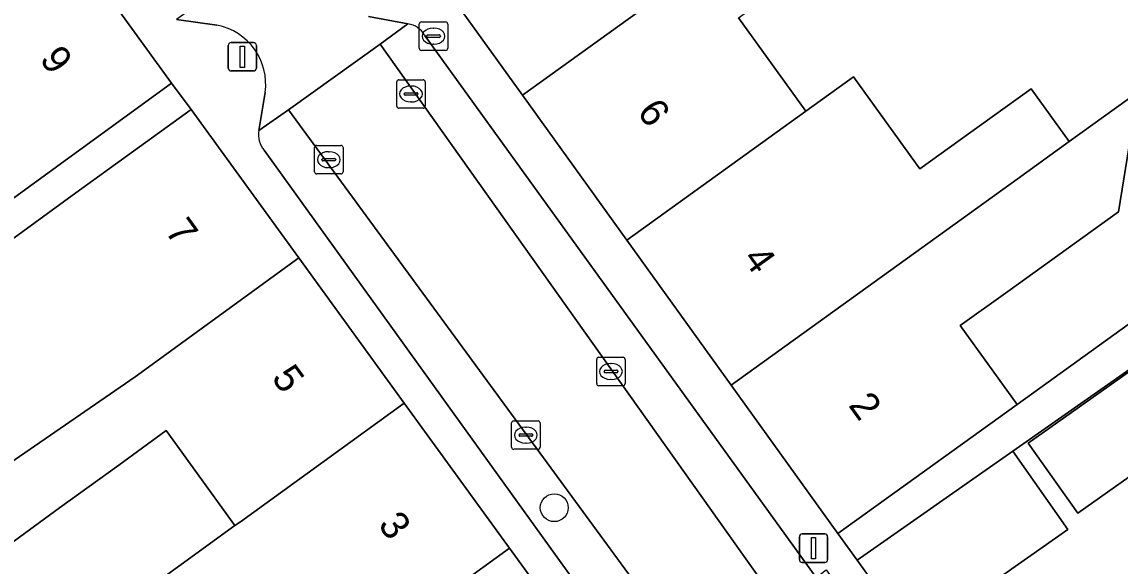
# Model space of a CAD drawing. Extents: x 161881 to 162523, y 381678 to 382381.
# Drawn here: x 162184.28 to 162222.87, y 381923.63 to 381942.76 of the extents above; entities that cross this region are included whole.
import ezdxf

# ---------------------------------------------------------------- set-up
doc = ezdxf.new("R2010")
doc.units = 0
for name, color, linetype in [('IMGEO_Boom', 7, 'Continuous'), ('IMGEO_Brandkraan', 7, 'Continuous'), ('IMGEO_Erf', 7, 'Continuous'), ('IMGEO_Kolk', 7, 'Continuous'), ('IMGEO_Lichtmast', 7, 'Continuous'), ('IMGEO_Pand', 7, 'Continuous'), ('IMGEO_Pand_nummerreeks', 7, 'Continuous'), ('IMGEO_Parkeervlak_open', 7, 'Continuous'), ('IMGEO_Rijbaan_lokaal_open', 7, 'Continuous'), ('IMGEO_Voetpad_open', 7, 'Continuous')]:
    doc.layers.add(name, color=color, linetype=linetype)

msp = doc.modelspace()

# ---------------------------------------------------------------- linework, layer by layer
at = {"layer": 'IMGEO_Boom'}
msp.add_circle((162202.985, 381925.681), 0.489, dxfattribs=at)
at = {"layer": 'IMGEO_Brandkraan'}
for p, q in [((162198.318, 381942.755), (162199.17, 381942.755)), ((162198.243, 381941.829), (162198.243, 381942.681)), ((162198.731, 381942.535), (162198.756, 381942.535)), ((162199.244, 381942.681), (162199.244, 381941.829)), ((162198.502, 381942.249), (162198.502, 381942.261)), ((162198.94, 381942.212), (162198.542, 381942.212)), ((162198.545, 381942.298), (162198.943, 381942.298)), ((162198.754, 381941.975), (162198.729, 381941.975)), ((162198.986, 381942.261), (162198.986, 381942.249)), ((162199.17, 381941.755), (162198.318, 381941.755))]:
    msp.add_line(p, q, dxfattribs=at)
for points in [[(162198.318, 381942.755), (162199.17, 381942.755)], [(162198.243, 381941.829), (162198.243, 381942.681)], [(162199.244, 381942.681), (162199.244, 381941.829)], [(162199.17, 381941.755), (162198.318, 381941.755)]]:
    msp.add_lwpolyline(points, dxfattribs=at)
for centre, radius, start, end in [((162198.32, 381942.679), 0.0765, 91.552, 178.448), ((162198.32, 381942.679), 0.0765, 91.552, 178.448), ((162199.168, 381942.679), 0.0765, 1.552, 88.448), ((162199.168, 381942.679), 0.0765, 1.552, 88.448), ((162198.542, 381942.258), 0.0403, 85.8775, 175.7526), ((162198.539, 381942.248), 0.0366, 178.938, 274.7102), ((162198.943, 381942.255), 0.043, 264.8664, 352.4533), ((162198.947, 381942.26), 0.0386, 1.7309, 96.639), ((162198.32, 381941.831), 0.0765, 181.552, 268.448), ((162198.32, 381941.831), 0.0765, 181.552, 268.448), ((162199.168, 381941.831), 0.0765, 271.552, 358.448), ((162199.168, 381941.831), 0.0765, 271.552, 358.448)]:
    msp.add_arc(centre, radius, start, end, dxfattribs=at)
for centre, major_axis, ratio, start_param, end_param in [((162198.73, 381942.255), (-0.387, 0.002), 0.722429, 4.712389, 7.853982), ((162198.755, 381942.255), (-0.39, 0.002), 0.717154, 1.570796, 4.712389)]:
    msp.add_ellipse(centre, major_axis=major_axis, ratio=ratio, start_param=start_param, end_param=end_param, dxfattribs=at)
at = {"layer": 'IMGEO_Erf'}
for points in [[(162209.457, 381942.903), (162211.822, 381939.62), (162213.5, 381940.829), (162215.834, 381937.589), (162217.916, 381939.089), (162219.743, 381940.406), (162221.079, 381938.552), (162223.492, 381940.291), (162222.809, 381936.085), (162218.922, 381933.285), (162217.252, 381932.082), (162219.25, 381929.308), (162232.631, 381938.95)], [(162234.406, 381938.399), (162219.1, 381927.669), (162221.034, 381924.911), (162215.596, 381921.098), (162220.871, 381913.764), (162223.438, 381915.604), (162222.035, 381917.563), (162222.76, 381918.083), (162221.484, 381919.862), (162223.543, 381921.337)], [(162178.17, 381900.128), (162199.228, 381914.711), (162197.223, 381917.474), (162196.043, 381916.635), (162195.779, 381916.999), (162189.576, 381912.591), (162188.844, 381912.071), (162188.641, 381911.926), (162188.593, 381911.892), (162188.43, 381912.117), (162188.303, 381912.292), (162187.121, 381913.922), (162185.646, 381915.954), (162190.206, 381919.262), (162188.367, 381921.798), (162188.111, 381922.15), (162187.995, 381922.31), (162191.766, 381925.054), (162189.346, 381928.389), (162187.681, 381927.18), (162185.605, 381925.674), (162183.128, 381923.877)]]:
    msp.add_lwpolyline(points, dxfattribs=at)
msp.add_lwpolyline([(162221.38, 381925.484), (162219.634, 381927.948), (162224.002, 381931.042), (162225.747, 381928.578)], close=True, dxfattribs=at)
at = {"layer": 'IMGEO_Kolk'}
for p, q in [((162197.451, 381939.798), (162197.451, 381940.65)), ((162197.526, 381940.724), (162198.378, 381940.724)), ((162197.939, 381940.504), (162197.964, 381940.504)), ((162198.452, 381940.65), (162198.452, 381939.798)), ((162197.71, 381940.218), (162197.71, 381940.23)), ((162198.148, 381940.181), (162197.75, 381940.181)), ((162197.753, 381940.267), (162198.151, 381940.267)), ((162198.194, 381940.23), (162198.194, 381940.218)), ((162198.378, 381939.724), (162197.526, 381939.724)), ((162197.962, 381939.944), (162197.937, 381939.944)), ((162194.564, 381937.488), (162194.564, 381938.34)), ((162194.639, 381938.414), (162195.491, 381938.414)), ((162195.052, 381938.194), (162195.077, 381938.194)), ((162195.565, 381938.34), (162195.565, 381937.488)), ((162194.823, 381937.908), (162194.823, 381937.92)), ((162195.261, 381937.871), (162194.863, 381937.871)), ((162194.866, 381937.957), (162195.264, 381937.957)), ((162195.307, 381937.92), (162195.307, 381937.908)), ((162195.491, 381937.414), (162194.639, 381937.414)), ((162195.075, 381937.634), (162195.05, 381937.634)), ((162204.476, 381930.044), (162204.476, 381930.896)), ((162204.551, 381930.97), (162205.403, 381930.97)), ((162204.964, 381930.75), (162204.989, 381930.75)), ((162205.477, 381930.896), (162205.477, 381930.044)), ((162204.735, 381930.464), (162204.735, 381930.476)), ((162205.173, 381930.427), (162204.775, 381930.427)), ((162204.778, 381930.513), (162205.176, 381930.513)), ((162205.219, 381930.476), (162205.219, 381930.464)), ((162204.987, 381930.19), (162204.962, 381930.19)), ((162205.403, 381929.97), (162204.551, 381929.97)), ((162201.488, 381927.807), (162201.488, 381928.659)), ((162201.563, 381928.733), (162202.415, 381928.733)), ((162201.976, 381928.513), (162202.001, 381928.513)), ((162202.489, 381928.659), (162202.489, 381927.807)), ((162201.747, 381928.227), (162201.747, 381928.239)), ((162202.185, 381928.19), (162201.787, 381928.19)), ((162201.79, 381928.276), (162202.188, 381928.276)), ((162202.231, 381928.239), (162202.231, 381928.227)), ((162202.415, 381927.733), (162201.563, 381927.733)), ((162201.999, 381927.953), (162201.974, 381927.953))]:
    msp.add_line(p, q, dxfattribs=at)
for points in [[(162197.451, 381939.798), (162197.451, 381940.65)], [(162197.526, 381940.724), (162198.378, 381940.724)], [(162198.452, 381940.65), (162198.452, 381939.798)], [(162198.378, 381939.724), (162197.526, 381939.724)], [(162194.564, 381937.488), (162194.564, 381938.34)], [(162194.639, 381938.414), (162195.491, 381938.414)], [(162195.565, 381938.34), (162195.565, 381937.488)], [(162195.491, 381937.414), (162194.639, 381937.414)], [(162204.476, 381930.044), (162204.476, 381930.896)], [(162204.551, 381930.97), (162205.403, 381930.97)], [(162205.477, 381930.896), (162205.477, 381930.044)], [(162205.403, 381929.97), (162204.551, 381929.97)], [(162201.488, 381927.807), (162201.488, 381928.659)], [(162201.563, 381928.733), (162202.415, 381928.733)], [(162202.489, 381928.659), (162202.489, 381927.807)], [(162202.415, 381927.733), (162201.563, 381927.733)]]:
    msp.add_lwpolyline(points, dxfattribs=at)
for centre, radius, start, end in [((162197.528, 381940.648), 0.0765, 91.552, 178.448), ((162197.528, 381940.648), 0.0765, 91.552, 178.448), ((162198.376, 381940.648), 0.0765, 1.552, 88.448), ((162198.376, 381940.648), 0.0765, 1.552, 88.448), ((162197.75, 381940.227), 0.0403, 85.8775, 175.7526), ((162197.747, 381940.217), 0.0366, 178.938, 274.7102), ((162198.151, 381940.224), 0.043, 264.8664, 352.4533), ((162198.155, 381940.229), 0.0386, 1.7309, 96.639), ((162197.528, 381939.8), 0.0765, 181.552, 268.448), ((162197.528, 381939.8), 0.0765, 181.552, 268.448), ((162198.376, 381939.8), 0.0765, 271.552, 358.448), ((162198.376, 381939.8), 0.0765, 271.552, 358.448), ((162194.641, 381938.338), 0.0765, 91.552, 178.448), ((162194.641, 381938.338), 0.0765, 91.552, 178.448), ((162195.489, 381938.338), 0.0765, 1.552, 88.448), ((162195.489, 381938.338), 0.0765, 1.552, 88.448), ((162194.863, 381937.917), 0.0403, 85.8775, 175.7526), ((162194.86, 381937.907), 0.0366, 178.938, 274.7102), ((162195.264, 381937.914), 0.043, 264.8664, 352.4533), ((162195.268, 381937.919), 0.0386, 1.7309, 96.639), ((162194.641, 381937.49), 0.0765, 181.552, 268.448), ((162194.641, 381937.49), 0.0765, 181.552, 268.448), ((162195.489, 381937.49), 0.0765, 271.552, 358.448), ((162195.489, 381937.49), 0.0765, 271.552, 358.448), ((162204.553, 381930.894), 0.0765, 91.552, 178.448), ((162204.553, 381930.894), 0.0765, 91.552, 178.448), ((162205.401, 381930.894), 0.0765, 1.552, 88.448), ((162205.401, 381930.894), 0.0765, 1.552, 88.448), ((162204.775, 381930.473), 0.0403, 85.8775, 175.7526), ((162204.772, 381930.463), 0.0366, 178.938, 274.7102), ((162205.176, 381930.47), 0.043, 264.8664, 352.4533), ((162205.18, 381930.475), 0.0386, 1.7309, 96.639), ((162204.553, 381930.046), 0.0765, 181.552, 268.448), ((162204.553, 381930.046), 0.0765, 181.552, 268.448), ((162205.401, 381930.046), 0.0765, 271.552, 358.448), ((162205.401, 381930.046), 0.0765, 271.552, 358.448), ((162201.565, 381928.657), 0.0765, 91.552, 178.448), ((162201.565, 381928.657), 0.0765, 91.552, 178.448), ((162202.413, 381928.657), 0.0765, 1.552, 88.448), ((162202.413, 381928.657), 0.0765, 1.552, 88.448), ((162201.787, 381928.236), 0.0403, 85.8775, 175.7526), ((162201.784, 381928.226), 0.0366, 178.938, 274.7102), ((162202.188, 381928.233), 0.043, 264.8664, 352.4533), ((162202.192, 381928.238), 0.0386, 1.7309, 96.639), ((162201.565, 381927.809), 0.0765, 181.552, 268.448), ((162201.565, 381927.809), 0.0765, 181.552, 268.448), ((162202.413, 381927.809), 0.0765, 271.552, 358.448), ((162202.413, 381927.809), 0.0765, 271.552, 358.448)]:
    msp.add_arc(centre, radius, start, end, dxfattribs=at)
for centre, major_axis, ratio, start_param, end_param in [((162197.938, 381940.224), (-0.387, 0.002), 0.722429, 4.712389, 7.853982), ((162197.963, 381940.224), (-0.39, 0.002), 0.717154, 1.570796, 4.712389), ((162195.051, 381937.914), (-0.387, 0.002), 0.722429, 4.712389, 7.853982), ((162195.076, 381937.914), (-0.39, 0.002), 0.717154, 1.570796, 4.712389), ((162204.963, 381930.47), (-0.387, 0.002), 0.722429, 4.712389, 7.853982), ((162204.988, 381930.47), (-0.39, 0.002), 0.717154, 1.570796, 4.712389), ((162201.975, 381928.233), (-0.387, 0.002), 0.722429, 4.712389, 7.853982), ((162202, 381928.233), (-0.39, 0.002), 0.717154, 1.570796, 4.712389)]:
    msp.add_ellipse(centre, major_axis=major_axis, ratio=ratio, start_param=start_param, end_param=end_param, dxfattribs=at)
at = {"layer": 'IMGEO_Lichtmast'}
for p, q in [((162191.629, 381942.032), (162192.419, 381942.032)), ((162192.419, 381942.032), (162191.629, 381942.032)), ((162191.529, 381941.132), (162191.529, 381941.932)), ((162191.529, 381941.932), (162191.529, 381941.132)), ((162192.519, 381941.932), (162192.519, 381941.132)), ((162192.519, 381941.132), (162192.519, 381941.932)), ((162192.419, 381941.032), (162191.629, 381941.032)), ((162191.629, 381941.032), (162192.419, 381941.032)), ((162211.599, 381923.858), (162211.599, 381924.658)), ((162211.599, 381924.658), (162211.599, 381923.858)), ((162211.699, 381924.758), (162212.489, 381924.758)), ((162212.489, 381924.758), (162211.699, 381924.758)), ((162212.589, 381924.658), (162212.589, 381923.858)), ((162212.589, 381923.858), (162212.589, 381924.658)), ((162212.489, 381923.758), (162211.699, 381923.758)), ((162211.699, 381923.758), (162212.489, 381923.758))]:
    msp.add_line(p, q, dxfattribs=at)
for points in [[(162191.949, 381941.907), (162192.099, 381941.907), (162192.099, 381941.157), (162191.949, 381941.157), (162191.949, 381941.907)], [(162212.019, 381924.633), (162212.169, 381924.633), (162212.169, 381923.883), (162212.019, 381923.883), (162212.019, 381924.633)]]:
    msp.add_lwpolyline(points, dxfattribs=at)
for centre, start, end in [((162191.629, 381941.932), 90, 180), ((162191.629, 381941.932), 90, 180), ((162192.419, 381941.932), 0, 90), ((162192.419, 381941.932), 360, 90), ((162191.629, 381941.132), 180, 270), ((162191.629, 381941.132), 180, 270), ((162192.419, 381941.132), 270, 0), ((162192.419, 381941.132), 270, 0), ((162211.699, 381924.658), 90, 180), ((162211.699, 381924.658), 90, 180), ((162212.489, 381924.658), 0, 90), ((162212.489, 381924.658), 360, 90), ((162211.699, 381923.858), 180, 270), ((162211.699, 381923.858), 180, 270), ((162212.489, 381923.858), 270, 0), ((162212.489, 381923.858), 270, 0)]:
    msp.add_arc(centre, 0.1, start, end, dxfattribs=at)
at = {"layer": 'IMGEO_Pand'}
for points in [[(162211.962, 381947.457), (162215.354, 381949.9), (162214.607, 381950.938), (162214.442, 381951.166), (162214.016, 381951.758), (162210.624, 381949.314), (162208.553, 381947.822), (162206.259, 381951.071), (162198.203, 381945.276), (162201.866, 381940.184)], [(162209.457, 381942.903), (162211.221, 381944.174), (162213.266, 381945.647), (162211.962, 381947.457), (162201.866, 381940.184), (162205.532, 381935.088), (162211.822, 381939.62)], [(162189.54, 381940.599), (162185.784, 381945.777), (162180.044, 381941.612), (162176.016, 381938.823), (162176.166, 381938.62), (162177.393, 381936.963), (162177.512, 381936.802), (162179.617, 381938.361), (162178.961, 381939.247), (162180.577, 381940.444), (162183.594, 381936.286), (162185.493, 381937.664)], [(162221.079, 381938.552), (162219.743, 381940.406), (162217.916, 381939.089), (162215.834, 381937.589), (162213.5, 381940.829), (162211.822, 381939.62), (162205.532, 381935.088), (162209.198, 381929.992), (162219.251, 381937.235)], [(162217.252, 381932.082), (162218.922, 381933.285), (162222.809, 381936.085), (162223.492, 381940.291), (162221.079, 381938.552), (162219.251, 381937.235), (162209.198, 381929.992), (162212.953, 381924.771), (162217.332, 381927.926), (162219.25, 381929.308)], [(162194.014, 381934.46), (162190.227, 381939.679), (162186.18, 381936.744), (162184.317, 381935.392), (162180.807, 381932.845), (162180.345, 381932.509), (162182.442, 381929.619), (162177.857, 381926.29), (162177.579, 381925.594), (162178.868, 381923.817), (162181.737, 381925.793), (162188.26, 381930.286)], [(162197.713, 381929.361), (162194.014, 381934.46), (162188.26, 381930.286), (162181.737, 381925.793), (162183.128, 381923.877), (162185.605, 381925.674), (162187.681, 381927.18), (162189.346, 381928.389), (162191.766, 381925.054), (162191.96, 381925.187)], [(162224.002, 381931.042), (162219.634, 381927.948), (162221.38, 381925.484), (162225.747, 381928.578)], [(162201.412, 381924.261), (162197.713, 381929.361), (162191.96, 381925.187), (162191.766, 381925.054), (162187.995, 381922.31), (162188.111, 381922.15), (162188.367, 381921.798), (162190.206, 381919.262), (162185.646, 381915.954), (162187.121, 381913.922), (162195.66, 381920.088)], [(162215.596, 381921.098), (162221.034, 381924.911), (162219.1, 381927.669), (162213.628, 381923.833)], [(162201.412, 381924.261), (162195.66, 381920.088), (162187.121, 381913.922), (162188.303, 381912.292), (162188.43, 381912.117), (162188.593, 381911.892), (162188.641, 381911.926), (162188.844, 381912.071), (162189.576, 381912.591), (162195.779, 381916.999), (162196.043, 381916.635), (162197.223, 381917.474), (162199.228, 381914.711), (162201.152, 381916.107), (162205.042, 381918.928), (162205.199, 381919.042)]]:
    msp.add_lwpolyline(points, close=True, dxfattribs=at)
at = {"layer": 'IMGEO_Parkeervlak_open'}
for points in [[(162197.845, 381942.684), (162196.865, 381941.979), (162221.938, 381906.686)], [(162221.861, 381909.804), (162214.799, 381919.58), (162212.193, 381923.231), (162198.431, 381942.294)], [(162193.648, 381939.662), (162192.603, 381938.942)], [(162211.441, 381915.372), (162193.648, 381939.662)], [(162192.794, 381938.247), (162206.572, 381919.103)]]:
    msp.add_lwpolyline(points, dxfattribs=at)
for centre, radius, start, end in [((162197.74, 381941.891), 0.8, 30.2669, 82.4433), ((162193.451, 381938.801), 0.86, 170.5782, 220.1552)]:
    msp.add_arc(centre, radius, start, end, dxfattribs=at)
at = {"layer": 'IMGEO_Rijbaan_lokaal_open'}
for points in [[(162194.772, 381945.533), (162195.028, 381946.682), (162193.973, 381945.919), (162190.764, 381943.599), (162189.716, 381942.842), (162191.13, 381942.643)], [(162192.827, 381940.274), (162192.603, 381938.942), (162193.648, 381939.662), (162196.865, 381941.979), (162197.845, 381942.684), (162196.463, 381942.947)], [(162225.828, 381902.52), (162222.15, 381906.388), (162221.938, 381906.686), (162196.865, 381941.979), (162193.648, 381939.662), (162211.441, 381915.372), (162215.131, 381910.302), (162219.356, 381904.234), (162221.423, 381900.229), (162222.089, 381899.341), (162222.611, 381898.266), (162226.939, 381901.305)]]:
    msp.add_lwpolyline(points, dxfattribs=at)
msp.add_arc((162190.741, 381940.572), 2.107, 351.8755, 79.3553, dxfattribs=at)
at = {"layer": 'IMGEO_Voetpad_open'}
for points in [[(162225.13, 381907.844), (162220.871, 381913.764), (162215.596, 381921.098), (162213.628, 381923.833), (162212.953, 381924.771), (162209.198, 381929.992), (162205.532, 381935.088), (162201.866, 381940.184), (162198.203, 381945.276), (162197.561, 381946.152), (162193.749, 381951.462), (162190.099, 381956.545), (162186.45, 381961.629), (162182.8, 381966.712), (162179.151, 381971.795), (162175.413, 381977.002), (162174.716, 381977.972), (162170.985, 381983.17)], [(162185.784, 381945.777), (162189.54, 381940.599), (162190.227, 381939.679), (162194.014, 381934.46), (162197.713, 381929.361), (162201.412, 381924.261), (162205.199, 381919.042), (162205.042, 381918.928), (162205.765, 381917.905), (162207.49, 381915.462), (162212.795, 381907.946), (162217.025, 381901.99), (162219.928, 381897.942), (162222.089, 381899.341), (162221.423, 381900.229), (162219.356, 381904.234), (162215.131, 381910.302), (162211.441, 381915.372)], [(162191.13, 381942.643), (162189.716, 381942.842)], [(162196.463, 381942.947), (162197.845, 381942.684)], [(162198.431, 381942.294), (162212.193, 381923.231), (162212.545, 381923.502), (162215.185, 381919.824), (162214.799, 381919.58), (162221.861, 381909.804)], [(162180.807, 381932.845), (162184.317, 381935.392), (162186.18, 381936.744), (162190.227, 381939.679), (162189.54, 381940.599), (162185.493, 381937.664), (162183.594, 381936.286)], [(162192.603, 381938.942), (162192.827, 381940.274)], [(162232.631, 381938.95), (162219.25, 381929.308), (162217.332, 381927.926), (162212.953, 381924.771), (162213.628, 381923.833), (162219.1, 381927.669), (162234.406, 381938.399)], [(162210.757, 381915.457), (162209.698, 381914.73), (162208.755, 381916.01), (162208.438, 381915.744), (162206.22, 381918.835), (162206.572, 381919.103), (162192.794, 381938.247)]]:
    msp.add_lwpolyline(points, dxfattribs=at)
for centre, radius, start, end in [((162190.741, 381940.572), 2.107, 351.8755, 79.3553), ((162197.74, 381941.891), 0.8, 30.2669, 82.4433), ((162193.451, 381938.801), 0.86, 170.5782, 220.1552)]:
    msp.add_arc(centre, radius, start, end, dxfattribs=at)

# ---------------------------------------------------------------- texts
at = {"layer": 'IMGEO_Pand_nummerreeks'}
for s, rotation, p in [('9', 305.9586, (162184.876, 381941.444)), ('6', 305.7695, (162205.872, 381939.589)), ('7', 305.9586, (162189.283, 381935.396)), ('4', 305.768, (162209.587, 381934.433)), ('5', 305.9606, (162193.025, 381930.237)), ('2', 305.7695, (162213.3, 381929.279)), ('3', 305.9586, (162196.769, 381925.078))]:
    msp.add_text(s, height=1, rotation=rotation, dxfattribs=at).set_placement(p)

doc.saveas('drawing.dxf')
